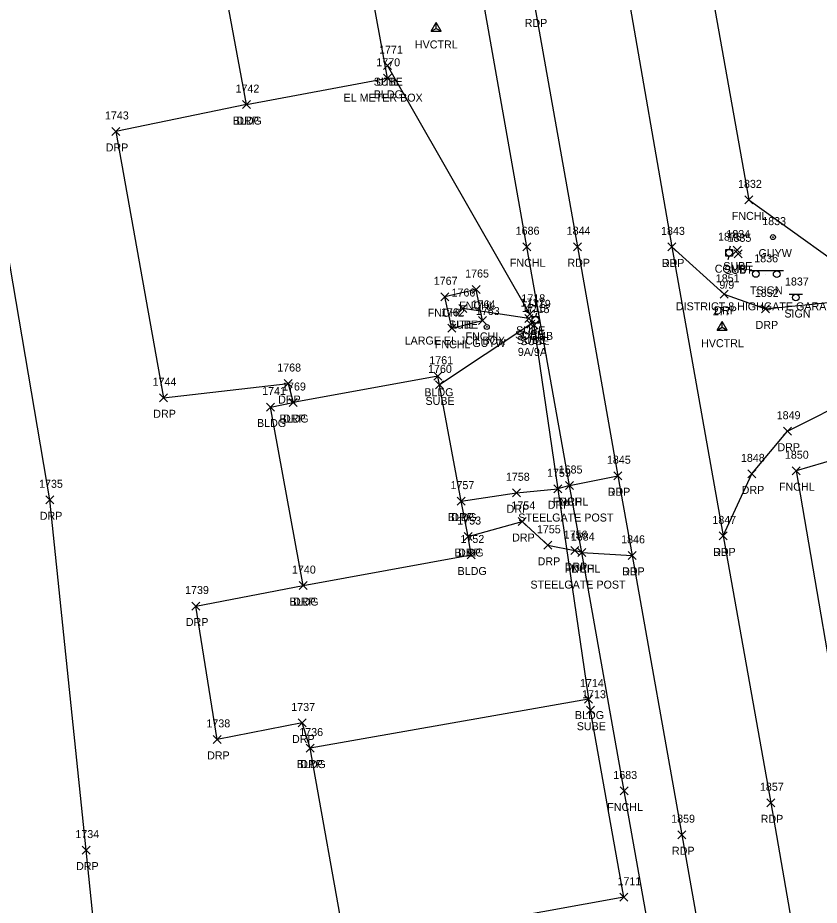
# Model space of a CAD drawing. Extents: x 1481523 to 1489083, y 884156 to 893756.
# Drawn here: x 1486450.8 to 1486651.1, y 888317 to 888538.8 of the extents above; entities that cross this region are included whole.
import ezdxf

# ---------------------------------------------------------------- set-up
doc = ezdxf.new("R2010")
doc.units = 0
for name, color, linetype in [('C_A', 7, 'Continuous'), ('C_I', 7, 'Continuous'), ('CPSM', 7, 'Continuous'), ('L_A', 7, 'Continuous'), ('L_C', 7, 'Continuous'), ('L_I', 7, 'Continuous'), ('L_TIC', 7, 'Continuous'), ('LBC', 7, 'Continuous'), ('LFNC', 7, 'Continuous'), ('P_A', 7, 'Continuous'), ('P_I', 7, 'Continuous'), ('P_TIC', 7, 'Continuous'), ('PET', 7, 'Continuous'), ('R_A', 7, 'Continuous'), ('R_I', 7, 'Continuous'), ('R_TIC', 7, 'Continuous'), ('RDP', 7, 'Continuous'), ('S_A', 7, 'Continuous'), ('S_C', 7, 'Continuous'), ('S_I', 7, 'Continuous'), ('SSGN', 7, 'Continuous'), ('U_A', 7, 'Continuous'), ('U_C', 7, 'Continuous'), ('U_I', 7, 'Continuous'), ('U_TIC', 7, 'Continuous'), ('UDEFAULT', 7, 'Continuous'), ('UE', 7, 'Continuous'), ('UP', 7, 'Continuous'), ('UPGW', 7, 'Continuous')]:
    doc.layers.add(name, color=color, linetype=linetype)

msp = doc.modelspace()

# ---------------------------------------------------------------- linework, layer by layer
at = {"layer": 'CPSM'}
for p, q in [((1486554.08, 888535.37), (1486555.33, 888537.54)), ((1486554.08, 888535.37), (1486555.33, 888536.09)), ((1486556.58, 888535.37), (1486555.33, 888537.54)), ((1486555.33, 888536.09), (1486555.33, 888537.54)), ((1486555.33, 888536.09), (1486555.33, 888536.09)), ((1486555.33, 888536.09), (1486556.58, 888535.37)), ((1486554.08, 888535.37), (1486556.58, 888535.37)), ((1486625.59, 888460.72), (1486626.84, 888462.89)), ((1486628.09, 888460.72), (1486626.84, 888462.89)), ((1486626.84, 888461.44), (1486626.84, 888462.89)), ((1486625.59, 888460.72), (1486626.84, 888461.44)), ((1486625.59, 888460.72), (1486628.09, 888460.72)), ((1486626.84, 888461.44), (1486626.84, 888461.44)), ((1486626.84, 888461.44), (1486628.09, 888460.72))]:
    msp.add_line(p, q, dxfattribs=at)
at = {"layer": 'L_TIC'}
for points in [[(1486542.14, 888522.63), (1486544.14, 888524.63)], [(1486544.14, 888522.63), (1486542.14, 888524.63)], [(1486506.89, 888516.06), (1486508.89, 888518.06)], [(1486508.89, 888516.06), (1486506.89, 888518.06)], [(1486506.89, 888516.06), (1486508.89, 888518.06)], [(1486508.89, 888516.06), (1486506.89, 888518.06)], [(1486632.47, 888492.25), (1486634.47, 888494.25)], [(1486634.47, 888492.25), (1486632.47, 888494.25)], [(1486577, 888480.54), (1486579, 888482.54)], [(1486579, 888480.54), (1486577, 888482.54)], [(1486564.32, 888469.85), (1486566.32, 888471.85)], [(1486566.32, 888469.85), (1486564.32, 888471.85)], [(1486556.47, 888468.03), (1486558.47, 888470.03)], [(1486558.47, 888468.03), (1486556.47, 888470.03)], [(1486556.47, 888468.03), (1486558.47, 888470.03)], [(1486558.47, 888468.03), (1486556.47, 888470.03)], [(1486565.94, 888462.14), (1486567.94, 888464.14)], [(1486567.94, 888462.14), (1486565.94, 888464.14)], [(1486558.25, 888460.16), (1486560.25, 888462.16)], [(1486560.25, 888460.16), (1486558.25, 888462.16)], [(1486558.25, 888460.16), (1486560.25, 888462.16)], [(1486560.25, 888460.16), (1486558.25, 888462.16)], [(1486554.79, 888448.18), (1486556.79, 888450.18)], [(1486556.79, 888448.18), (1486554.79, 888450.18)], [(1486518.57, 888441.61), (1486520.57, 888443.61)], [(1486520.57, 888441.61), (1486518.57, 888443.61)], [(1486518.57, 888441.61), (1486520.57, 888443.61)], [(1486520.57, 888441.61), (1486518.57, 888443.61)], [(1486512.96, 888440.49), (1486514.96, 888442.49)], [(1486514.96, 888440.49), (1486512.96, 888442.49)], [(1486644.27, 888424.57), (1486646.27, 888426.57)], [(1486646.27, 888424.57), (1486644.27, 888426.57)], [(1486587.69, 888420.87), (1486589.69, 888422.87)], [(1486589.69, 888420.87), (1486587.69, 888422.87)], [(1486560.61, 888416.97), (1486562.61, 888418.97)], [(1486562.61, 888416.97), (1486560.61, 888418.97)], [(1486562.31, 888408.12), (1486564.31, 888410.12)], [(1486564.31, 888408.12), (1486562.31, 888410.12)], [(1486563.1, 888403.51), (1486565.1, 888405.51)], [(1486565.1, 888403.51), (1486563.1, 888405.51)], [(1486590.72, 888404.11), (1486592.72, 888406.11)], [(1486592.72, 888404.11), (1486590.72, 888406.11)], [(1486521.07, 888395.86), (1486523.07, 888397.86)], [(1486523.07, 888395.86), (1486521.07, 888397.86)], [(1486521.07, 888395.86), (1486523.07, 888397.86)], [(1486523.07, 888395.86), (1486521.07, 888397.86)], [(1486592.41, 888367.51), (1486594.41, 888369.51)], [(1486594.41, 888367.51), (1486592.41, 888369.51)], [(1486522.87, 888355.26), (1486524.87, 888357.26)], [(1486524.87, 888355.26), (1486522.87, 888357.26)], [(1486522.87, 888355.26), (1486524.87, 888357.26)], [(1486524.87, 888355.26), (1486522.87, 888357.26)], [(1486601.35, 888344.54), (1486603.35, 888346.54)], [(1486603.35, 888344.54), (1486601.35, 888346.54)], [(1486601.21, 888317.97), (1486603.21, 888319.97)], [(1486603.21, 888317.97), (1486601.21, 888319.97)], [(1486601.21, 888317.97), (1486603.21, 888319.97)], [(1486603.21, 888317.97), (1486601.21, 888319.97)]]:
    msp.add_lwpolyline(points, dxfattribs=at)
at = {"layer": 'LBC'}
for points in [[(1486507.89, 888517.06), (1486484.32, 888644.4), (1486519.89, 888650.91)], [(1486507.89, 888517.06), (1486543.14, 888523.63), (1486519.89, 888650.91)], [(1486522.07, 888396.86), (1486564.1, 888404.51), (1486563.31, 888409.12), (1486561.61, 888417.97), (1486555.79, 888449.18), (1486519.57, 888442.61)], [(1486522.07, 888396.86), (1486513.96, 888441.49), (1486519.57, 888442.61)], [(1486602.21, 888318.97), (1486593.41, 888368.51), (1486523.87, 888356.26)], [(1486602.21, 888318.97), (1486532.76, 888306.44), (1486523.87, 888356.26)]]:
    msp.add_lwpolyline(points, dxfattribs=at)
at = {"layer": 'LFNC'}
for points in [[(1486494.1, 888089.15), (1486542.31, 888096.89), (1486562.09, 888100.11), (1486610.33, 888107.69), (1486643.08, 888113.16), (1486633.4, 888171.45), (1486626.62, 888209.7), (1486614.5, 888277.37), (1486602.35, 888345.54), (1486591.72, 888405.11), (1486588.69, 888421.87), (1486578, 888481.54), (1486565.98, 888549.48), (1486554.04, 888616.26), (1486540.66, 888690.96), (1486537.54, 888707.46), (1486527.52, 888764.64), (1486517.54, 888822.03), (1486505.67, 888889.2), (1486493.41, 888956.36), (1486481.11, 889023.64), (1486470.56, 889080.63), (1486461.7, 889127.71), (1486454.26, 889166.3)], [(1486611.93, 888614.86), (1486623.3, 888550.21), (1486633.47, 888493.25), (1486665.01, 888470.64)], [(1486559.25, 888461.16), (1486566.94, 888463.14), (1486565.32, 888470.85), (1486557.47, 888469.03)], [(1486559.25, 888461.16), (1486557.47, 888469.03)], [(1486670.36, 888445.6), (1486672.6, 888433.56), (1486645.27, 888425.57), (1486658.68, 888347.28), (1486674.66, 888255.66), (1486685.97, 888189.5), (1486715.15, 888190.21)]]:
    msp.add_lwpolyline(points, dxfattribs=at)
at = {"layer": 'P_TIC'}
for points in [[(1486589.64, 888480.54), (1486591.64, 888482.54)], [(1486591.64, 888480.54), (1486589.64, 888482.54)], [(1486613.23, 888480.5), (1486615.23, 888482.5)], [(1486615.23, 888480.5), (1486613.23, 888482.5)], [(1486599.71, 888423.31), (1486601.71, 888425.31)], [(1486601.71, 888423.31), (1486599.71, 888425.31)], [(1486626.06, 888408.28), (1486628.06, 888410.28)], [(1486628.06, 888408.28), (1486626.06, 888410.28)], [(1486603.32, 888403.42), (1486605.32, 888405.42)], [(1486605.32, 888403.42), (1486603.32, 888405.42)], [(1486637.94, 888341.58), (1486639.94, 888343.58)], [(1486639.94, 888341.58), (1486637.94, 888343.58)], [(1486615.77, 888333.61), (1486617.77, 888335.61)], [(1486617.77, 888333.61), (1486615.77, 888335.61)]]:
    msp.add_lwpolyline(points, dxfattribs=at)
at = {"layer": 'PET'}
for points in [[(1486482.46, 889213.8), (1486493.22, 889156.8), (1486512.17, 889057.76), (1486527.58, 888974.51), (1486542.53, 888889.08), (1486553.79, 888825.37), (1486565.07, 888760.91), (1486577.19, 888690.78), (1486591.4, 888610.57), (1486602.78, 888547.25), (1486614.23, 888481.5), (1486627.06, 888409.28), (1486638.94, 888342.58), (1486654.61, 888252.22), (1486669.1, 888181.27), (1486680.17, 888112.03), (1486680.99, 888105.73)], [(1486459.06, 889211.36), (1486470.75, 889147.47), (1486504.42, 888970.47), (1486519.24, 888886.05), (1486530.77, 888821.38), (1486542.03, 888758.69), (1486549.22, 888711.97), (1486553.24, 888690.65), (1486568.55, 888607.7), (1486579.98, 888541.46), (1486590.64, 888481.54), (1486600.71, 888424.31), (1486604.32, 888404.42), (1486616.77, 888334.61), (1486631.96, 888248.32), (1486646.36, 888167.9), (1486656.21, 888114.83)]]:
    msp.add_lwpolyline(points, dxfattribs=at)
at = {"layer": 'R_TIC'}
for points in [[(1486506.89, 888516.06), (1486508.89, 888518.06)], [(1486508.89, 888516.06), (1486506.89, 888518.06)], [(1486474.25, 888509.35), (1486476.25, 888511.35)], [(1486476.25, 888509.35), (1486474.25, 888511.35)], [(1486613.23, 888480.5), (1486615.23, 888482.5)], [(1486615.23, 888480.5), (1486613.23, 888482.5)], [(1486626.34, 888468.66), (1486628.34, 888470.66)], [(1486628.34, 888468.66), (1486626.34, 888470.66)], [(1486636.68, 888465), (1486638.68, 888467)], [(1486638.68, 888465), (1486636.68, 888467)], [(1486517.35, 888446.35), (1486519.35, 888448.35)], [(1486519.35, 888446.35), (1486517.35, 888448.35)], [(1486486.15, 888442.8), (1486488.15, 888444.8)], [(1486488.15, 888442.8), (1486486.15, 888444.8)], [(1486518.57, 888441.61), (1486520.57, 888443.61)], [(1486520.57, 888441.61), (1486518.57, 888443.61)], [(1486642.14, 888434.44), (1486644.14, 888436.44)], [(1486644.14, 888434.44), (1486642.14, 888436.44)], [(1486599.71, 888423.31), (1486601.71, 888425.31)], [(1486601.71, 888423.31), (1486599.71, 888425.31)], [(1486633.2, 888423.78), (1486635.2, 888425.78)], [(1486635.2, 888423.78), (1486633.2, 888425.78)], [(1486587.69, 888420.87), (1486589.69, 888422.87)], [(1486589.69, 888420.87), (1486587.69, 888422.87)], [(1486587.69, 888420.87), (1486589.69, 888422.87)], [(1486589.69, 888420.87), (1486587.69, 888422.87)], [(1486574.45, 888419.05), (1486576.45, 888421.05)], [(1486576.45, 888419.05), (1486574.45, 888421.05)], [(1486584.74, 888420.05), (1486586.74, 888422.05)], [(1486586.74, 888420.05), (1486584.74, 888422.05)], [(1486584.74, 888420.05), (1486586.74, 888422.05)], [(1486586.74, 888420.05), (1486584.74, 888422.05)], [(1486457.78, 888417.3), (1486459.78, 888419.3)], [(1486459.78, 888417.3), (1486457.78, 888419.3)], [(1486560.61, 888416.97), (1486562.61, 888418.97)], [(1486562.61, 888416.97), (1486560.61, 888418.97)], [(1486575.84, 888411.88), (1486577.84, 888413.88)], [(1486577.84, 888411.88), (1486575.84, 888413.88)], [(1486562.31, 888408.12), (1486564.31, 888410.12)], [(1486564.31, 888408.12), (1486562.31, 888410.12)], [(1486626.06, 888408.28), (1486628.06, 888410.28)], [(1486628.06, 888408.28), (1486626.06, 888410.28)], [(1486582.2, 888405.93), (1486584.2, 888407.93)], [(1486584.2, 888405.93), (1486582.2, 888407.93)], [(1486588.95, 888404.6), (1486590.95, 888406.6)], [(1486590.95, 888404.6), (1486588.95, 888406.6)], [(1486588.95, 888404.6), (1486590.95, 888406.6)], [(1486590.95, 888404.6), (1486588.95, 888406.6)], [(1486590.72, 888404.11), (1486592.72, 888406.11)], [(1486592.72, 888404.11), (1486590.72, 888406.11)], [(1486590.72, 888404.11), (1486592.72, 888406.11)], [(1486592.72, 888404.11), (1486590.72, 888406.11)], [(1486603.32, 888403.42), (1486605.32, 888405.42)], [(1486605.32, 888403.42), (1486603.32, 888405.42)], [(1486521.07, 888395.86), (1486523.07, 888397.86)], [(1486523.07, 888395.86), (1486521.07, 888397.86)], [(1486494.29, 888390.76), (1486496.29, 888392.76)], [(1486496.29, 888390.76), (1486494.29, 888392.76)], [(1486520.82, 888361.53), (1486522.82, 888363.53)], [(1486522.82, 888361.53), (1486520.82, 888363.53)], [(1486499.6, 888357.43), (1486501.6, 888359.43)], [(1486501.6, 888357.43), (1486499.6, 888359.43)], [(1486522.87, 888355.26), (1486524.87, 888357.26)], [(1486524.87, 888355.26), (1486522.87, 888357.26)], [(1486466.85, 888329.77), (1486468.85, 888331.77)], [(1486468.85, 888329.77), (1486466.85, 888331.77)]]:
    msp.add_lwpolyline(points, dxfattribs=at)
at = {"layer": 'RDP'}
for points in [[(1486570.58, 888134.65), (1486496.65, 888122.37), (1486474.92, 888261.77), (1486467.85, 888330.77), (1486458.78, 888418.3), (1486415.84, 888670.58), (1486400.74, 888672.5), (1486301.22, 888657.33)], [(1486614.23, 888481.5), (1486627.34, 888469.66), (1486637.68, 888466), (1486655.78, 888467.86), (1486665.71, 888469.79), (1486697.98, 888477.57), (1486758.59, 888490.27), (1486807.02, 888500.11), (1486830.76, 888505.1), (1486855.7, 888510.65), (1486857.86, 888511.81), (1486859.69, 888514.5), (1486859.68, 888517.32), (1486859.32, 888519.19), (1486854.8, 888538.4)], [(1486507.89, 888517.06), (1486475.25, 888510.35), (1486487.15, 888443.8), (1486518.35, 888447.35), (1486519.57, 888442.61)], [(1486627.06, 888409.28), (1486634.2, 888424.78), (1486643.14, 888435.44), (1486660.74, 888444.3), (1486670.7, 888447.41), (1486703.54, 888453.36), (1486762.17, 888464.63), (1486810.87, 888474.09), (1486835.34, 888373.21), (1486845.25, 888329.26)], [(1486588.69, 888421.87), (1486600.71, 888424.31)], [(1486561.61, 888417.97), (1486575.45, 888420.05), (1486585.74, 888421.05)], [(1486588.69, 888421.87), (1486585.74, 888421.05)], [(1486563.31, 888409.12), (1486576.84, 888412.88), (1486583.2, 888406.93), (1486589.95, 888405.6)], [(1486591.72, 888405.11), (1486589.95, 888405.6)], [(1486591.72, 888405.11), (1486604.32, 888404.42)], [(1486523.87, 888356.26), (1486521.82, 888362.53), (1486500.6, 888358.43), (1486495.29, 888391.76), (1486522.07, 888396.86)]]:
    msp.add_lwpolyline(points, dxfattribs=at)
at = {"layer": 'SSGN'}
for p, q in [((1486633.57, 888475.57), (1486642.16, 888475.57)), ((1486637.59, 888474.67), (1486637.59, 888474.67)), ((1486643.57, 888469.7), (1486646.91, 888469.7)), ((1486645.22, 888468.87), (1486645.22, 888468.87))]:
    msp.add_line(p, q, dxfattribs=at)
for centre in [(1486635.23, 888474.74), (1486640.44, 888474.67), (1486645.22, 888468.87)]:
    msp.add_circle(centre, 0.833, dxfattribs=at)
at = {"layer": 'U_TIC'}
for points in [[(1486542.17, 888525.79), (1486544.17, 888527.79)], [(1486544.17, 888525.79), (1486542.17, 888527.79)], [(1486629.55, 888479.71), (1486631.55, 888481.71)], [(1486631.55, 888479.71), (1486629.55, 888481.71)], [(1486629.85, 888478.77), (1486631.85, 888480.77)], [(1486631.85, 888478.77), (1486629.85, 888480.77)], [(1486560.97, 888465.1), (1486562.97, 888467.1)], [(1486562.97, 888465.1), (1486560.97, 888467.1)], [(1486577.76, 888463.66), (1486579.76, 888465.66)], [(1486579.76, 888463.66), (1486577.76, 888465.66)], [(1486577.53, 888462.58), (1486579.53, 888464.58)], [(1486579.53, 888462.58), (1486577.53, 888464.58)], [(1486577.96, 888461.23), (1486579.96, 888463.23)], [(1486579.96, 888461.23), (1486577.96, 888463.23)], [(1486578.83, 888460.96), (1486580.83, 888462.96)], [(1486580.83, 888460.96), (1486578.83, 888462.96)], [(1486555.13, 888446.02), (1486557.13, 888448.02)], [(1486557.13, 888446.02), (1486555.13, 888448.02)], [(1486592.93, 888364.72), (1486594.93, 888366.72)], [(1486594.93, 888364.72), (1486592.93, 888366.72)]]:
    msp.add_lwpolyline(points, dxfattribs=at)
at = {"layer": 'UDEFAULT'}
for points in [[(1486542.17, 888525.79), (1486544.17, 888527.79)], [(1486544.17, 888525.79), (1486542.17, 888527.79)], [(1486560.97, 888465.1), (1486562.97, 888467.1)], [(1486562.97, 888465.1), (1486560.97, 888467.1)]]:
    msp.add_lwpolyline(points, dxfattribs=at)
at = {"layer": 'UE'}
for points in [[(1486578.76, 888464.66), (1486543.17, 888526.79)], [(1486578.53, 888463.58), (1486561.97, 888466.1)], [(1486578.96, 888462.23), (1486556.13, 888447.02)], [(1486593.93, 888365.72), (1486579.83, 888461.96)]]:
    msp.add_lwpolyline(points, dxfattribs=at)
at = {"layer": 'UP'}
for p, q in [((1486627.73, 888479.21), (1486627.73, 888480.88)), ((1486627.73, 888480.88), (1486629.39, 888480.88)), ((1486628.81, 888481.71), (1486628.56, 888480.88)), ((1486629.39, 888480.88), (1486629.39, 888479.21)), ((1486629.39, 888479.21), (1486627.73, 888479.21)), ((1486628.31, 888478.38), (1486628.56, 888479.21)), ((1486628.56, 888480.05), (1486628.56, 888480.05)), ((1486580.4, 888464.94), (1486580.15, 888464.1)), ((1486579.32, 888462.44), (1486579.32, 888464.1)), ((1486579.32, 888464.1), (1486580.99, 888464.1)), ((1486580.15, 888463.27), (1486580.15, 888463.27)), ((1486580.99, 888464.1), (1486580.99, 888462.44)), ((1486580.99, 888462.44), (1486579.32, 888462.44)), ((1486579.9, 888461.6), (1486580.15, 888462.44))]:
    msp.add_line(p, q, dxfattribs=at)
for centre in [(1486628.56, 888480.05), (1486580.15, 888463.27)]:
    msp.add_circle(centre, 0.833, dxfattribs=at)
at = {"layer": 'UPGW'}
for centre, radius in [((1486639.51, 888483.94), 0.625), ((1486639.51, 888483.94), 0.0833), ((1486567.98, 888461.49), 0.625), ((1486567.98, 888461.49), 0.0833)]:
    msp.add_circle(centre, radius, dxfattribs=at)

# ---------------------------------------------------------------- texts
at = {"layer": 'C_A'}
for p in [(1486550.02, 888531.09), (1486621.54, 888456.44)]:
    msp.add_text('HVCTRL', height=2, dxfattribs=at).set_placement(p)
at = {"layer": 'C_I'}
msp.add_text('277', height=2, dxfattribs=at).set_placement((1486624.48, 888464.44))
at = {"layer": 'L_A'}
for s, p in [('BLDG', (1486539.74, 888518.63)), ('BLDG', (1486504.48, 888512.06)), ('BLDG', (1486504.48, 888512.06)), ('FNCHL', (1486629.22, 888488.25)), ('FNCHL', (1486573.75, 888476.54)), ('FNCHL', (1486561.07, 888465.85)), ('FNCHL', (1486553.22, 888464.03)), ('FNCHL', (1486553.22, 888464.03)), ('FNCHL', (1486555, 888456.16)), ('FNCHL', (1486555, 888456.16)), ('FNCHL', (1486562.69, 888458.14)), ('BLDG', (1486552.38, 888444.18)), ('BLDG', (1486510.56, 888436.49)), ('BLDG', (1486516.16, 888437.61)), ('BLDG', (1486516.16, 888437.61)), ('FNCHL', (1486641.01, 888420.57)), ('FNCHL', (1486584.44, 888416.87)), ('BLDG', (1486558.2, 888412.97)), ('BLDG', (1486559.9, 888404.12)), ('BLDG', (1486560.69, 888399.51)), ('FNCHL', (1486587.46, 888400.11)), ('BLDG', (1486518.66, 888391.86)), ('BLDG', (1486518.66, 888391.86)), ('BLDG', (1486590, 888363.51)), ('BLDG', (1486520.46, 888351.26)), ('BLDG', (1486520.46, 888351.26)), ('FNCHL', (1486598.1, 888340.54))]:
    msp.add_text(s, height=2, dxfattribs=at).set_placement(p)
at = {"layer": 'L_C'}
for p in [(1486575.86, 888412.87), (1486578.89, 888396.11)]:
    msp.add_text('STEELGATE POST', height=2, dxfattribs=at).set_placement(p)
at = {"layer": 'L_I'}
for s, p in [('1770', (1486540.37, 888526.63)), ('1742', (1486505.19, 888520.06)), ('1742', (1486505.19, 888520.06)), ('1832', (1486630.78, 888496.25)), ('1686', (1486575.2, 888484.54)), ('1765', (1486562.58, 888473.85)), ('1767', (1486554.73, 888472.03)), ('1767', (1486554.73, 888472.03)), ('1764', (1486564.2, 888466.14)), ('1762', (1486556.51, 888464.16)), ('1762', (1486556.51, 888464.16)), ('1761', (1486553.62, 888452.18)), ('1769', (1486516.82, 888445.61)), ('1769', (1486516.82, 888445.61)), ('1741', (1486511.84, 888444.49)), ('1850', (1486642.49, 888428.57)), ('1685', (1486585.95, 888424.87)), ('1757', (1486558.92, 888420.97)), ('1753', (1486560.61, 888412.12)), ('1752', (1486561.4, 888407.51)), ('1684', (1486588.98, 888408.11)), ('1740', (1486519.29, 888399.86)), ('1740', (1486519.29, 888399.86)), ('1714', (1486591.28, 888371.51)), ('1736', (1486521.12, 888359.26)), ('1736', (1486521.12, 888359.26)), ('1683', (1486599.61, 888348.54)), ('1711', (1486600.65, 888321.97)), ('1711', (1486600.65, 888321.97))]:
    msp.add_text(s, height=2, dxfattribs=at).set_placement(p)
at = {"layer": 'P_A'}
for p in [(1486577.46, 888536.46), (1486588.13, 888476.54), (1486611.72, 888476.5), (1486598.19, 888419.31), (1486624.54, 888404.28), (1486601.8, 888399.42), (1486636.43, 888337.58), (1486614.26, 888329.61)]:
    msp.add_text('RDP', height=2, dxfattribs=at).set_placement(p)
at = {"layer": 'P_I'}
for s, p in [('1844', (1486587.95, 888484.54)), ('1843', (1486611.54, 888484.5)), ('1845', (1486598.01, 888427.31)), ('1847', (1486624.36, 888412.28)), ('1846', (1486601.57, 888407.42)), ('1857', (1486636.25, 888345.58)), ('1859', (1486614.07, 888337.61))]:
    msp.add_text(s, height=2, dxfattribs=at).set_placement(p)
at = {"layer": 'R_A'}
for p in [(1486505.38, 888512.06), (1486472.74, 888505.35), (1486611.72, 888476.5), (1486624.83, 888464.66), (1486635.16, 888461), (1486515.83, 888442.35), (1486484.63, 888438.8), (1486517.05, 888437.61), (1486640.63, 888430.44), (1486598.19, 888419.31), (1486631.68, 888419.78), (1486586.18, 888416.87), (1486586.18, 888416.87), (1486572.94, 888415.05), (1486583.23, 888416.05), (1486583.23, 888416.05), (1486456.27, 888413.3), (1486559.1, 888412.97), (1486574.32, 888407.88), (1486560.79, 888404.12), (1486624.54, 888404.28), (1486580.69, 888401.93), (1486587.44, 888400.6), (1486587.44, 888400.6), (1486589.2, 888400.11), (1486589.2, 888400.11), (1486601.8, 888399.42), (1486519.55, 888391.86), (1486492.77, 888386.76), (1486519.3, 888357.53), (1486498.09, 888353.43), (1486521.36, 888351.26), (1486465.34, 888325.77)]:
    msp.add_text('DRP', height=2, dxfattribs=at).set_placement(p)
at = {"layer": 'R_I'}
for s, p in [('1742', (1486505.19, 888520.06)), ('1743', (1486472.55, 888513.35)), ('1843', (1486611.54, 888484.5)), ('1851', (1486625.22, 888472.66)), ('1852', (1486634.98, 888469)), ('1768', (1486515.61, 888450.35)), ('1744', (1486484.45, 888446.8)), ('1769', (1486516.82, 888445.61)), ('1849', (1486640.44, 888438.44)), ('1845', (1486598.01, 888427.31)), ('1848', (1486631.5, 888427.78)), ('1758', (1486572.76, 888423.05)), ('1759', (1486583.04, 888424.05)), ('1759', (1486583.04, 888424.05)), ('1685', (1486585.95, 888424.87)), ('1685', (1486585.95, 888424.87)), ('1735', (1486456.09, 888421.3)), ('1757', (1486558.92, 888420.97)), ('1754', (1486574.14, 888415.88)), ('1753', (1486560.61, 888412.12)), ('1847', (1486624.36, 888412.28)), ('1755', (1486580.51, 888409.93)), ('1756', (1486587.2, 888408.6)), ('1756', (1486587.2, 888408.6)), ('1684', (1486588.98, 888408.11)), ('1684', (1486588.98, 888408.11)), ('1846', (1486601.57, 888407.42)), ('1740', (1486519.29, 888399.86)), ('1739', (1486492.58, 888394.76)), ('1737', (1486519.12, 888365.53)), ('1738', (1486497.91, 888361.43)), ('1736', (1486521.12, 888359.26)), ('1734', (1486465.16, 888333.77))]:
    msp.add_text(s, height=2, dxfattribs=at).set_placement(p)
at = {"layer": 'S_A'}
for s, p in [('TSIGN', (1486633.76, 888469.65)), ('SIGN', (1486642.36, 888463.85))]:
    msp.add_text(s, height=2, dxfattribs=at).set_placement(p)
at = {"layer": 'S_C'}
msp.add_text('DISTRICT 8 HIGHGATE GARAGE', height=2, dxfattribs=at).set_placement((1486615.25, 888465.65))
at = {"layer": 'S_I'}
for s, p in [('1836', (1486634.83, 888477.65)), ('1837', (1486642.51, 888471.85))]:
    msp.add_text(s, height=2, dxfattribs=at).set_placement(p)
at = {"layer": 'U_A'}
for s, p in [('SUBE', (1486539.71, 888521.79)), ('UTIL', (1486540.34, 888521.79)), ('GUYW', (1486635.91, 888478.94)), ('COMB', (1486624.95, 888475.05)), ('SUBE', (1486627.09, 888475.71)), ('SUBT', (1486627.35, 888474.77)), ('SUBE', (1486558.51, 888461.1)), ('UTIL', (1486559.13, 888461.1)), ('SUBE', (1486575.07, 888458.58)), ('SUBE', (1486575.3, 888459.66)), ('GUYW', (1486564.37, 888456.49)), ('SUBE', (1486575.5, 888457.23)), ('SUBE', (1486576.36, 888456.96)), ('COMB', (1486576.54, 888458.27)), ('SUBE', (1486552.66, 888442.02)), ('SUBE', (1486590.47, 888360.72))]:
    msp.add_text(s, height=2, dxfattribs=at).set_placement(p)
at = {"layer": 'U_C'}
for s, p in [('EL METER BOX', (1486532.2, 888517.79)), ('9/9', (1486626.11, 888471.05)), ('LARGE EL JCT BOX', (1486547.45, 888457.1)), ('9A/9A', (1486575.75, 888454.27))]:
    msp.add_text(s, height=2, dxfattribs=at).set_placement(p)
at = {"layer": 'U_I'}
for s, p in [('1771', (1486541.05, 888529.79)), ('1771', (1486541.05, 888529.79)), ('1833', (1486636.82, 888486.94)), ('1870', (1486625.78, 888483.05)), ('1834', (1486627.86, 888483.71)), ('1835', (1486628.16, 888482.77)), ('1766', (1486559.17, 888469.1)), ('1766', (1486559.17, 888469.1)), ('1718', (1486576.64, 888467.66)), ('1717', (1486576.4, 888466.58)), ('1716', (1486576.78, 888465.23)), ('1719', (1486578.02, 888466.27)), ('1763', (1486565.24, 888464.49)), ('1715', (1486577.7, 888464.96)), ('1760', (1486553.3, 888450.02)), ('1713', (1486591.81, 888368.72))]:
    msp.add_text(s, height=2, dxfattribs=at).set_placement(p)

doc.saveas('drawing.dxf')
